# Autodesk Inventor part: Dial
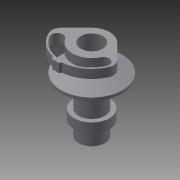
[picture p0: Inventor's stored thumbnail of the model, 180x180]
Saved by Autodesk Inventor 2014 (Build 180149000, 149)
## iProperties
Shininess: 64.0
Length Units: 11272
Angle Units: 11279
Time Units: 11290
Mass Units: 11286
Length Display Precision: 3
Angle Display Precision: 2
Compacted: True
Created: 2001-11
Part Number: Dial
Document SubType Name: Modeling
Designer: Autodesk, Inc.
Mass: 1.02961 g
Surface Area: 19.0281 cm^2
Volume: 1.02961 cm^3
Density: 1 g/cm^3
Material: Generic
Appearance: Grey (Light)
Density: 0.0
Volumn: 0.0
Area: 0.0
PropertySet Name: Model Information
Control State: 0
Master: False
Checked Out: False
Author: Autodesk, Inc.
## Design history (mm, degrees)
sketch "Sketch1"
  geometry: L1 (120.263, 98.09)-(121.533, 98.09); L2 (121.533, 100.63)-(121.533, 98.09); L3 (121.533, 100.63)-(125.343, 100.63); L4 (125.343, 101.458)-(125.343, 100.63); L5 (119.755, 103.715)-(125.343, 101.458); L6 (119.755, 106.472)-(119.755, 103.715); L7 (119.755, 106.472)-(125.851, 106.472); L8 (125.851, 106.472)-(125.851, 109.012); L9 (116.453, 109.012)-(125.851, 109.012); L10 (116.453, 109.012)-(116.453, 86.66); L11 (116.453, 86.66)-(117.215, 86.66); L12 (117.215, 86.66)-(117.215, 85.644); L13 (117.215, 85.644)-(120.263, 85.644); L14 (120.263, 89.708)-(120.263, 85.644); L15 (120.263, 89.708)-(121.533, 89.708); L16 (121.533, 92.502)-(121.533, 89.708); L17 (120.263, 92.502)-(121.533, 92.502); L18 (120.263, 98.09)-(120.263, 92.502); L19 (116.453, 109.012)-(116.453, 86.66)
  constraints: 38 end point, 9 vertical, 8 horizontal, 2 collinear, 1 other
  dimensions: "d1" = 9.398 distance of L9.start L8.end; "d3" = 22.352 distance of L9.start L10.end; "d5" = 2.54 distance of L7.end L8.end; "d11" = 10.922 vertical distance of L9.start L1.end; "d13" = 8.382 vertical distance of L9.start L3.end; "d15" = 16.51 vertical distance of L16.start L8.end; "d17" = 19.304 vertical distance of L14.start L8.end; "d19" = 1.016 distance of L11.end L12.end; "d23" = 8.89 horizontal distance of L10.end L3.end; "d25" = 0.762 distance of L10.end L11.end; "d27" = 3.048 distance of L12.end L13.end; "d51" = 6.604 diameter of L6 L10
revolve "RevolutionFull1" sketch "Sketch1" stored, may be unused: angle "d28" = 360 deg
sketch "Sketch2"
  geometry: C1 r 3.302 at (0, 0) reference; A1 r 5.588 centre (0, 0) between (-4.761, -2.925) and (5.042, -2.408); A2 r 1.651 centre (6.532, -3.12) between (7.607, -1.867) and (5.042, -2.408); A3 r 1.651 centre (6.532, -3.12) between (8.022, -3.832) and (7.607, -1.867); A4 r 8.89 centre (0, 0) between (-7.575, -4.654) and (8.022, -3.832); A5 r 1.651 centre (-6.168, -3.79) between (-7.335, -2.622) and (-7.575, -4.654); A6 r 1.651 centre (-6.168, -3.79) between (-4.761, -2.925) and (-7.335, -2.622)
  constraints: 12 point on circle, 6 centre point, 5 tangent, 4 concentric
  dimensions: "d34" = 12.7 horizontal distance of A6.centre A3.centre; "d36" = 5.588 radius of A1; "d38" = 8.89 radius of A4
extrude "ExtrusionToFace1" cut sketch "Sketch2" stored distance "d39" = 3.302; taper "d40" = 0 deg
sketch "Sketch3"
  geometry: L1 (25.051, 17.256)-(-16.734, 17.256); L2 (25.051, -5.225)-(25.051, 17.256); L3 (25.051, -5.225)-(10.165, -5.225); L4 (3.682, 3.682)-(9.59, -2.226); L5 (-3.682, 3.682)-(-9.632, -2.268); L6 (-16.734, -6.364)-(-10.09, -5.233); L7 (-16.734, 17.256)-(-16.734, -6.364); C1 r 9.398 at (0, 0) reference; A1 r 2.721 centre (7.666, -4.15) between (10.165, -5.225) and (9.59, -2.226); A2 r 5.207 centre (0, 0) between (3.682, 3.682) and (-3.682, 3.682); A3 r 2.54 centre (-7.836, -4.064) between (-9.632, -2.268) and (-10.09, -5.233)
  constraints: 14 end point, 6 point on circle, 4 tangent, 3 centre point, 2 horizontal, 2 vertical, 1 concentric
extrude "ExtrusionBlind1" cut sketch "Sketch3" distance "d41" = 2.54; taper "d42" = 0 deg
sketch "Sketch4"
  geometry: L1 (-1.536, -9.906)-(0.457, -9.906); L2 (0.457, -9.906)-(0.734, -9.369); L3 (-1.536, -9.906)-(-2.352, -9.099); A1 r 9.398 centre (0, 0) between (-9.214, -1.85) and (9.214, -1.85) reference
  constraints: 6 end point, 2 point on circle, 1 horizontal, 1 other
  dimensions: "d44" = 9.906 dimension on L1.start
extrude "ExtrusionToPlane1" join sketch "Sketch4" stored distance "d45" = 3.302; taper "d46" = 0 deg
extrude "ExtrusionThru1" cut stored distance "d49" = 3.302; taper "d50" = 0 deg
  node "Sketch5" dims "d48" = 6.35
fillet "Fillet1" dims "d52" = 2.54
body "Solid1"
other parameters: "d0" = 9.398 (derived), "d2" = 22.352 (derived), "d4" = 2.54 (derived), "d6" = 5.08 (derived), "d8" = 6.604 (derived), "d10" = 10.922 (derived), "d12" = 8.382 (derived), "d14" = 16.51 (derived), "d16" = 19.304 (derived), "d18" = 1.016 (derived), "d20" = 158 deg (derived), "d22" = 8.89 (derived), "d24" = 0.762 (derived), "d26" = 3.048 (derived), "d29" = 0, "d30" = 0, "d31" = 0, "d32" = 0, "d33" = 12.7 (derived), "d35" = 5.588 (derived), "d37" = 8.89 (derived), "d43" = 9.906 (derived), "d47" = 6.35 (derived)
